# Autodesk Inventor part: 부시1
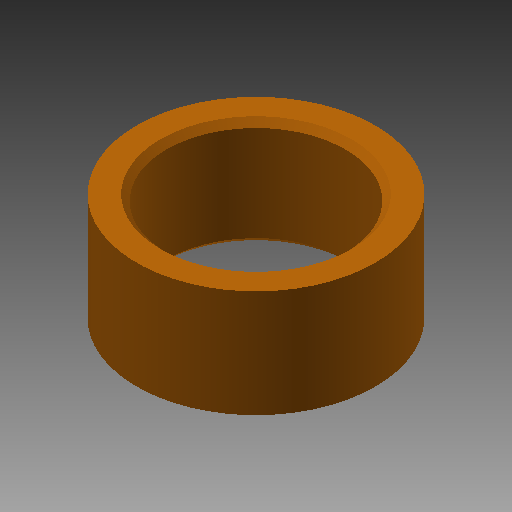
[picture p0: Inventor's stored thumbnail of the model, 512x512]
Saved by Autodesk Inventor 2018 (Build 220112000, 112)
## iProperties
Created: 2016-08
Part Number: 부시1
Material: 강철, 탄소
Document SubType Name: Modeling
Designer: mduedu
Density: 7.87 g/cm^3
Appearance: 주황색
Author: mduedu
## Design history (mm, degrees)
sketch "스케치1"
  geometry: C1 r 7.5 at (0, 0); C2 r 10 at (0, 0); 1 further point
  constraints: 2 centre point, 2 coincident
  dimensions: "d0" = 15 diameter of C1; "d1" = 20 diameter of C2
extrude "돌출1" new body sketch "스케치1" stored distance "d2" = 9; taper "d3" = 0 deg
chamfer "모따기1" distance "d4" = 0.5; stored, may be unused: second distance "d5" = 2, angle "d6" = 45 deg
node "솔리드1"
